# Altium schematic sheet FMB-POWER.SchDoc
size A4
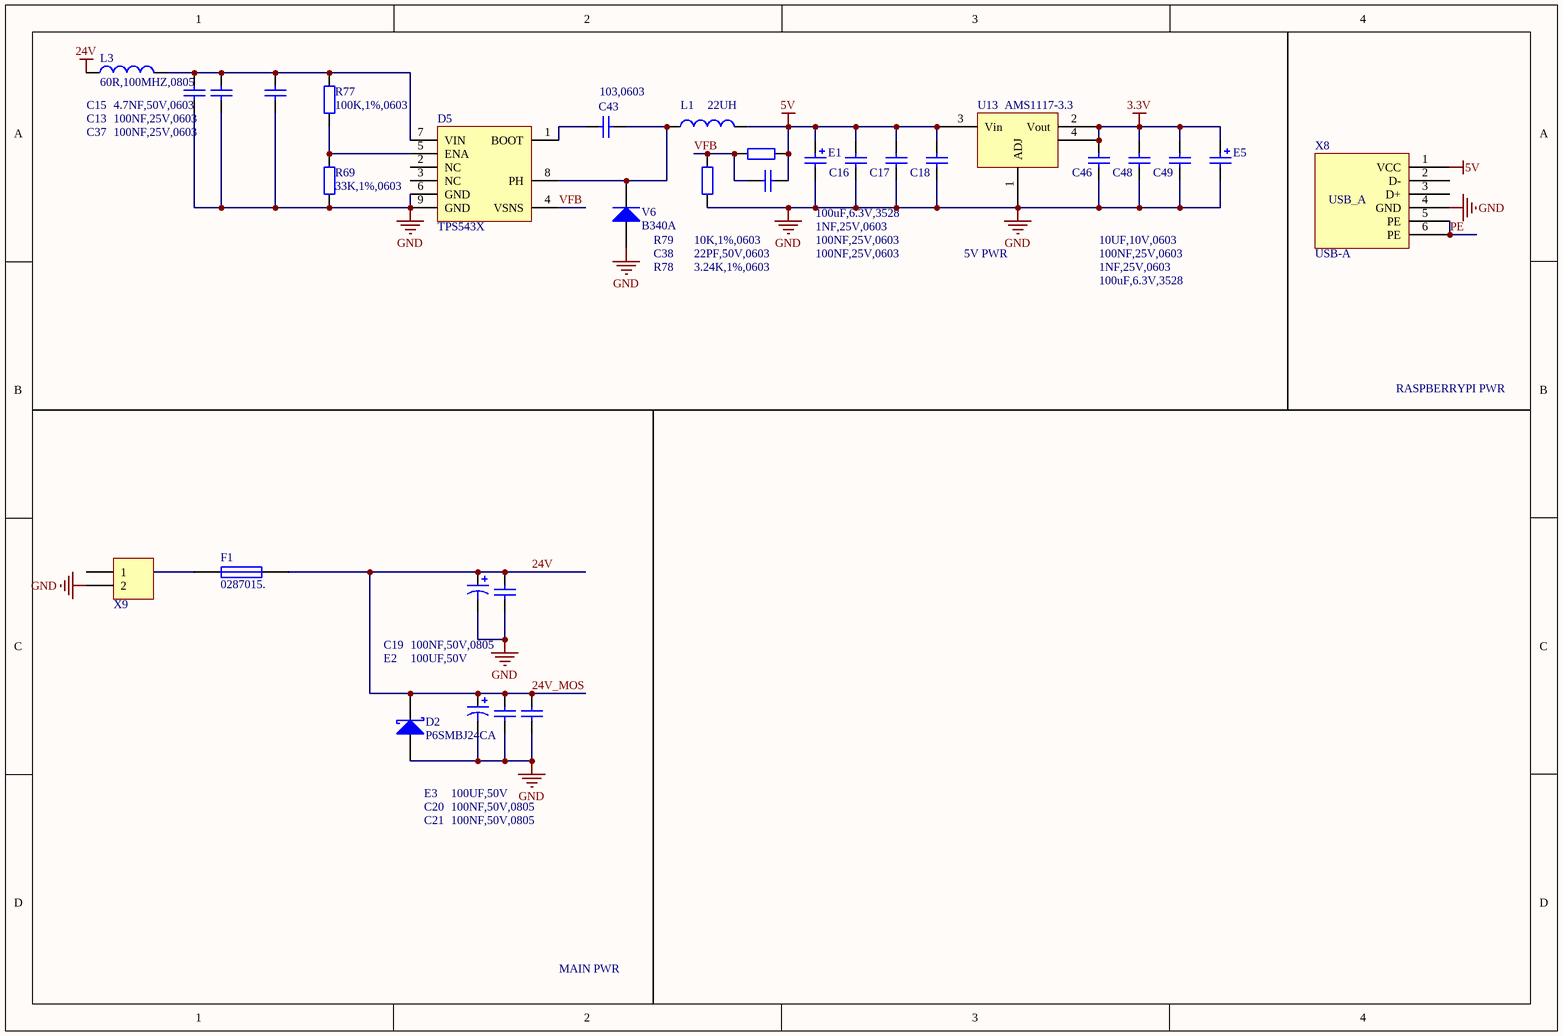
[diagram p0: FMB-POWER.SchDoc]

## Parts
C13  100NF,25V,0603  [RC0603]
C15  4.7NF,50V,0603  [RC0603]
C16  1NF,25V,0603  [RC0603]
C17  100NF,25V,0603  [RC0603]
C18  100NF,25V,0603  [RC0603]
C19  100NF,50V,0805  [RC0805]
C20  100NF,50V,0805  [RC0805]
C21  100NF,50V,0805  [RC0805]
C37  100NF,25V,0603  [RC0603]
C38  22PF,50V,0603  [RC0603]
C43  103,0603  [RC0603]
C46  100NF,25V,0603  [RC0603]
C48  10UF,10V,0603  [RC0603]
C49  1NF,25V,0603  [RC0603]
D2  P6SMBJ24CA  [SMB]
D5  TPS543X  [SO-8-1]
E1  100uF,6.3V,3528  [3528-21]
E2  100UF,50V  [RB-.2X.4]
E3  100UF,50V  [RB-.2X.4]
E5  value 100uF,6.3V,3528
F1  0287015.  [GF-C40]
L1  22UH  [L7*7]
L3  60R,100MHZ,0805  [RC0805]
R69  33K,1%,0603  [RC0603]
R77  100K,1%,0603  [RC0603]
R78  3.24K,1%,0603  [RC0603]
R79  10K,1%,0603  [RC0603]
U13  AMS1117-3.3  [SOT-223]
V6  B340A  [SMA]
X8  USB-A  [USB-A180]
X9  Molex 151048-1206  [151048]  (value not drawn)

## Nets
3.3V: C46.2 C48.2 C49.2 E5.1 U13.2(Vout) U13.4
5V: C16.2 C17.2 C18.2 C38.1 E1.1 L1.2 R79.2 U13.3(Vin) X8.1(VCC)
24V: C19.1 C20.1 C21.1 D2.2(K) E2.1 E3.1 F1.1 L3.1  [also labelled 24V_MOS]
GND: C13.2 C15.1 C16.1 C17.1 C18.1 C19.2 C20.2 C21.2 C37.2 C46.1 C48.1 C49.1 D2.1(A) D5.6(GND) D5.9(GND) E1.2 E2.2 E3.2 E5.2 R69.2 R78.2 U13.1(ADJ) V6.1(A) X8.4(GND) X9.2
PE: X8.5(PE) X8.6(PE)
VFB: C38.2 D5.4(VSNS) R78.1 R79.1
NetC13_1: C13.1 C15.2 C37.1 D5.7(VIN) L3.2 R77.1
NetC43_1: C43.1 D5.8(PH) L1.1 V6.2(K)
NetC43_2: C43.2 D5.1(BOOT)
NetD5_5: D5.5(ENA) R69.1 R77.2
NetF1_2: F1.2 X9.1

Not connected (* = marked no-connect by the designer): D5 2(NC) 3(NC); X8 2(D-) 3(D+)

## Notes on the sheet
- 5V PWR
- RASPBERRYPI PWR
- MAIN PWR

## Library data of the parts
C13 C15-C21 C37 C38 C43 C46 C48 C49 = Cap: Capacitor; Value: 100pF
D2 = D Schottky: Schottky Diode
E1 E5 = Cap Pol2: Polarized Capacitor (Axial)
E2 E3 = Cap Pol3: Polarized Capacitor (Surface Mount); Value: 100pF
F1 = Fuse 1: Fuse
L1 L3 = Inductor: Code_IEC: 1005; Value: 10mH
R69 R77-R79 = Res2: Resistor; Value: 1K
V6 = Diode: Default Diode
X9 = Header 2: Header, 2-Pin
